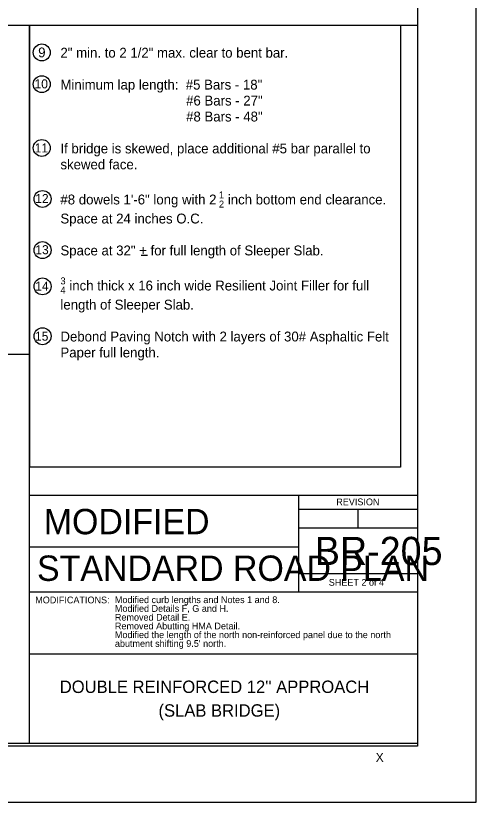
# Model space of a CAD drawing. Extents: x 10028 to 81668, y 6395 to 11634.
# Drawn here: x 19755 to 20572, y 7825 to 9219 of the extents above; entities that cross this region are included whole.
import ezdxf

# ---------------------------------------------------------------- set-up
doc = ezdxf.new("R2010")
doc.units = 0
for name, color, linetype in [('Constructions', 7, 'Continuous'), ('Default', 7, 'Continuous'), ('dsnCellElements', 7, 'Continuous'), ('dsnPaintPlaceStopLineWhite', 7, 'Continuous'), ('DsnShtInsideBorder', 7, 'Continuous'), ('dsnstdblockInterim', 7, 'Continuous'), ('dsnStdDimension', 7, 'Continuous'), ('dsnTextNote', 7, 'Continuous'), ('Level 5', 7, 'Continuous'), ('ShtPlotIdentification', 7, 'Continuous'), ('TextAlignmentSml', 7, 'Continuous')]:
    doc.layers.add(name, color=color, linetype=linetype)

msp = doc.modelspace()

# ---------------------------------------------------------------- linework, layer by layer
at = {"layer": 'Default'}
msp.add_lwpolyline([(17332.5, 9944), (20467.5, 9944), (20467.5, 7924), (17332.5, 7924)], close=True, dxfattribs=at)
at = {"layer": 'DsnShtInsideBorder'}
for p, q in [((19779.5, 9202.7), (19779.5, 8419)), ((20437.5, 9202.7), (20437.5, 8419)), ((20437.5, 8419), (19779.5, 8419))]:
    msp.add_line(p, q, dxfattribs=at)
at = {"layer": 'dsnstdblockInterim'}
msp.add_lwpolyline([(17332.5, 9939), (20467.5, 9939), (20467.5, 7929), (17332.5, 7929)], close=True, dxfattribs=at)
at = {"layer": 'dsnStdDimension'}
msp.add_lwpolyline([(17228, 7824.5), (20572, 7824.5), (20572, 10408.5), (17228, 10408.5)], close=True, dxfattribs=at)
at = {"layer": 'Level 5'}
for p, q in [((19779.5, 8369), (19779.5, 9202.7)), ((19977.5, 8794.6), (19988.6, 8794.6)), ((17332.5, 8619.4), (19779.5, 8619.4))]:
    msp.add_line(p, q, dxfattribs=at)
at = {"layer": 'ShtPlotIdentification'}
msp.add_line((17332.5, 9202.7), (20467.5, 9202.7), dxfattribs=at)
for centre in [(19801, 9154.2), (19801, 9097.9), (19801, 8984.8), (19802.5, 8894.4), (19802.5, 8803.8), (19802.5, 8739.4), (19802.5, 8651)]:
    msp.add_circle(centre, 15, dxfattribs=at)
at = {"layer": 'TextAlignmentSml'}
for p, q in [((20256.6, 8369), (20256.6, 8277.7)), ((20256.6, 8344.1), (20467.5, 8344.1)), ((20362.1, 8344.1), (20362.1, 8310.9)), ((20256.6, 8310.9), (20467.5, 8310.9)), ((19779.5, 8277.7), (20256.6, 8277.7)), ((20256.6, 8277.7), (20256.6, 8197.7)), ((20467.5, 8229.9), (20256.6, 8229.9)), ((19779.5, 8197.7), (20467.5, 8197.7)), ((19779.5, 8087.7), (20467.5, 8087.7))]:
    msp.add_line(p, q, dxfattribs=at)
msp.add_lwpolyline([(19779.5, 8369), (20467.5, 8369), (20467.5, 7929), (19779.5, 7929)], close=True, dxfattribs=at)

# ---------------------------------------------------------------- texts
at = {"layer": 'Constructions'}
msp.add_text('X', height=16, dxfattribs=at).set_placement((20393.6, 7896))
at = {"layer": 'dsnCellElements'}
msp.add_text('9', height=17.5, dxfattribs=at).set_placement((19794.7, 9145.5))
at = {"layer": 'dsnPaintPlaceStopLineWhite'}
for s, height, p in [('2" min. to 2 1/2" max. clear to bent bar.', 17.5, (19834.2, 9145)), ('Minimum lap length:  #5 Bars - 18"', 17.5, (19834.2, 9088.4)), ('  #6 Bars - 27"', 17.5, (20044.2, 9060.1)), ('  #8 Bars - 48"', 17.5, (20044.2, 9031.8)), ('If bridge is skewed, place additional #5 bar parallel to', 17.5, (19834.2, 8975.2)), ('skewed face.', 17.5, (19834.2, 8946.9)), ('#8 dowels 1\'-6" long with 2', 17.5, (19834.2, 8884.7)), ('1', 12.3, (20115.4, 8895.5)), (' inch bottom end clearance.', 17.5, (20124.7, 8884.7)), ('2', 12.3, (20115.4, 8879.2)), ('Space at 24 inches O.C.', 17.5, (19834.2, 8850.9)), ('Space at 32" + for full length of Sleeper Slab.', 17.5, (19834.2, 8794.3)), ('3', 12.3, (19834.2, 8742.9)), (' inch thick x 16 inch wide Resilient Joint Filler for full', 17.5, (19843.5, 8732.1)), ('4', 12.3, (19834.2, 8726.6)), ('length of Sleeper Slab.', 17.5, (19834.2, 8698.3)), ('Debond Paving Notch with 2 layers of 30# Asphaltic Felt', 17.5, (19834.2, 8641.7)), ('Paper full length.', 17.5, (19834.2, 8613.4))]:
    msp.add_text(s, height=height, dxfattribs=at).set_placement(p)
at = {"layer": 'dsnTextNote'}
for s, height, p in [('MODIFIED', 45, (19804.6, 8299.8)), ('MODIFICATIONS:', 12, (19789.5, 8177.3))]:
    msp.add_text(s, height=height, dxfattribs=at).set_placement(p)
at = {"layer": 'ShtPlotIdentification'}
for s, p in [('10', (19788.2, 9090.5)), ('11', (19788.5, 8976.8)), ('12', (19789.4, 8887.1)), ('13', (19789.6, 8796.4)), ('14', (19789.4, 8731.7)), ('15', (19789.1, 8643))]:
    msp.add_text(s, height=16, dxfattribs=at).set_placement(p)
at = {"layer": 'TextAlignmentSml'}
for s, height, p in [('REVISION', 12, (20323.6, 8351.2)), ('BR-205', 50, (20285.5, 8245.2)), ('STANDARD ROAD PLAN', 45.001, (19792.6, 8217.1)), ('SHEET 2 of 4', 12, (20310.3, 8208.5)), ('Modified curb lengths and Notes 1 and 8.', 12, (19930.8, 8177.7)), ('Modified Details F, G and H.', 12, (19930.8, 8162.2)), ('Removed Detail E.', 12, (19930.8, 8146.6)), ('Removed Abutting HMA Detail.', 12, (19930.8, 8131.1)), ('Modified the length of the north non-reinforced panel due to the north', 12, (19930.8, 8115.6)), ("abutment shifting 9.5' north.", 12, (19930.8, 8100.1)), ("DOUBLE REINFORCED 12'' APPROACH", 22, (19833, 8018.3)), ('(SLAB BRIDGE)', 22, (20008.2, 7976.3))]:
    msp.add_text(s, height=height, dxfattribs=at).set_placement(p)

doc.saveas('drawing.dxf')
